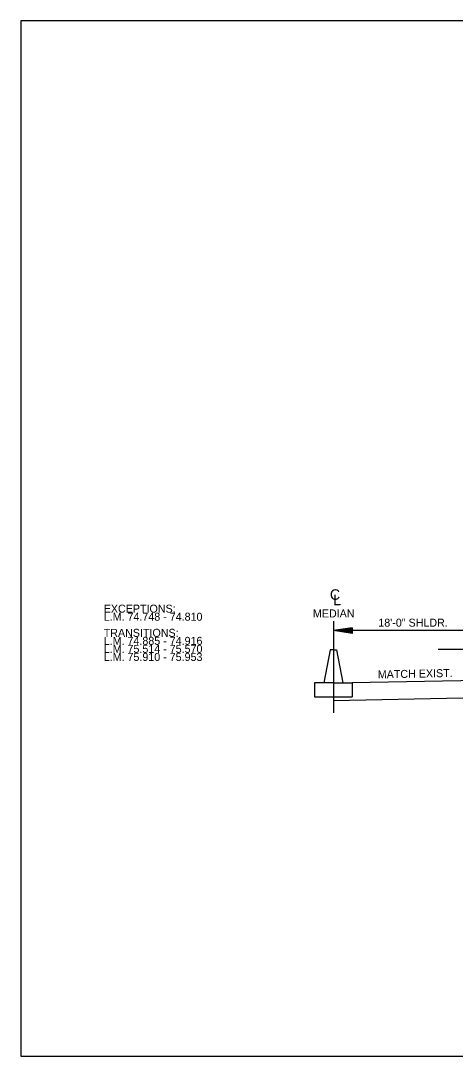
# Model space of a CAD drawing. Extents: x 2261938 to 2263136, y -3124572 to -3124216.
# Drawn here: x 2262328.1 to 2262374.3, y -3124556.1 to -3124446.1 of the extents above; entities that cross this region are included whole.
import ezdxf

# ---------------------------------------------------------------- set-up
doc = ezdxf.new("R2010")
doc.units = 0
for name, color, linetype in [('DSN_DRFT_Common-Annotations', 7, 'Continuous'), ('DSN_DRFT_Common-Line', 7, 'Continuous'), ('DSN_DRFT_Dimension', 7, 'Continuous')]:
    doc.layers.add(name, color=color, linetype=linetype)

msp = doc.modelspace()

# ---------------------------------------------------------------- linework, layer by layer
at = {"layer": 'DSN_DRFT_Common-Line'}
for p, q in [((2262361.33, -3124509.88), (2262361.33, -3124519.63)), ((2262361, -3124512.94), (2262360.33, -3124516.44)), ((2262361.33, -3124512.94), (2262361, -3124512.94)), ((2262361.33, -3124512.94), (2262361.67, -3124512.94)), ((2262361.67, -3124512.94), (2262362.33, -3124516.44)), ((2262391.33, -3124515.88), (2262363.33, -3124516.44)), ((2262359.33, -3124516.44), (2262359.33, -3124517.94)), ((2262361.33, -3124516.44), (2262359.33, -3124516.44)), ((2262361.33, -3124516.44), (2262363.33, -3124516.44)), ((2262363.33, -3124516.44), (2262363.33, -3124517.94)), ((2262359.33, -3124517.94), (2262363.33, -3124517.94)), ((2262391.33, -3124517.75), (2262361.33, -3124518.35))]:
    msp.add_line(p, q, dxfattribs=at)
msp.add_lwpolyline([(2262328.11, -3124446.1), (2262328.11, -3124556.1), (2262498.11, -3124556.1), (2262498.11, -3124446.1)], close=True, dxfattribs=at)
at = {"layer": 'DSN_DRFT_Dimension'}
for p, q in [((2262363.33, -3124510.58), (2262361.33, -3124510.88)), ((2262379.33, -3124510.88), (2262361.33, -3124510.88)), ((2262363.33, -3124511.18), (2262361.33, -3124510.88)), ((2262363.33, -3124510.63), (2262361.67, -3124510.88)), ((2262363.33, -3124511.13), (2262361.67, -3124510.88)), ((2262363.33, -3124510.68), (2262362.01, -3124510.88)), ((2262363.33, -3124511.08), (2262362.01, -3124510.88)), ((2262363.33, -3124510.73), (2262362.34, -3124510.88)), ((2262363.33, -3124511.03), (2262362.34, -3124510.88)), ((2262363.33, -3124510.78), (2262362.68, -3124510.88)), ((2262363.33, -3124510.97), (2262362.68, -3124510.88)), ((2262363.33, -3124510.83), (2262363.02, -3124510.88)), ((2262363.33, -3124510.92), (2262363.02, -3124510.88)), ((2262363.33, -3124510.58), (2262363.33, -3124511.18)), ((2262376.33, -3124512.88), (2262372.47, -3124512.88))]:
    msp.add_line(p, q, dxfattribs=at)

# ---------------------------------------------------------------- texts
at = {"layer": 'DSN_DRFT_Common-Annotations'}
for s, height, p in [('C', 1.12, (2262360.98, -3124507.63)), ('L', 1.12, (2262361.33, -3124508.2)), ('MATCH EXIST.', 0.85, (2262366.06, -3124515.97))]:
    msp.add_text(s, height=height, rotation=1.1458, dxfattribs=at).set_placement(p)
for s, p in [('EXCEPTIONS:', (2262336.93, -3124508.98)), ('L.M. 74.748 - 74.810', (2262336.93, -3124509.84)), ('MEDIAN', (2262359.16, -3124509.49)), ('18\'-0" SHLDR.', (2262366.11, -3124510.47)), ('TRANSITIONS:', (2262336.93, -3124511.55)), ('L.M. 74.885 - 74.916', (2262336.93, -3124512.4)), ('L.M. 75.514 - 75.570', (2262336.93, -3124513.25)), ('L.M. 75.910 - 75.953', (2262336.93, -3124514.11))]:
    msp.add_text(s, height=0.85, dxfattribs=at).set_placement(p)

doc.saveas('drawing.dxf')
